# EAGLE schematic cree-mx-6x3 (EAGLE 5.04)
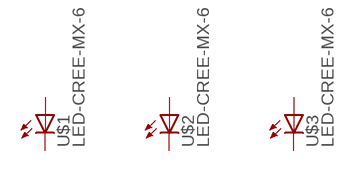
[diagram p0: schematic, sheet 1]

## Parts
U$1  LED-CREE-MX-6  [LED-CREE-MX-6]
U$2  LED-CREE-MX-6  [LED-CREE-MX-6]
U$3  LED-CREE-MX-6  [LED-CREE-MX-6]
Unconnected: U$1.P$1(A) U$1.P$2(C) U$2.P$1(A) U$2.P$2(C) U$3.P$1(A) U$3.P$2(C)

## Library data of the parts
U$1-U$3 = trl:LED-CREE-MX-6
